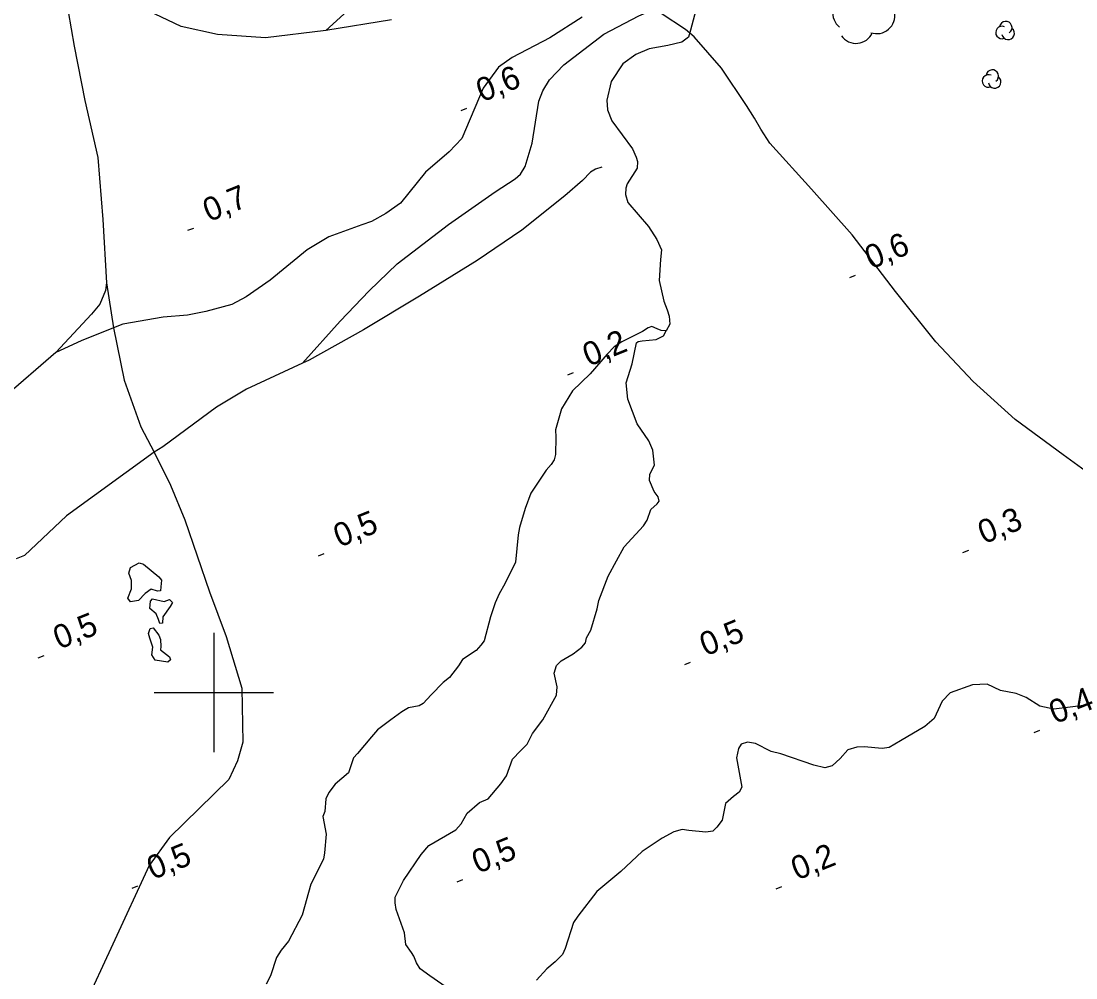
# Model space of a CAD drawing. Extents: x 362852 to 366875, y 5563573 to 5566479.
# Drawn here: x 363367.7 to 363544.5, y 5564552.2 to 5564712.5 of the extents above; entities that cross this region are included whole.
import ezdxf

# ---------------------------------------------------------------- set-up
doc = ezdxf.new("R2010")
doc.units = 0
for name, color, linetype in [('Niveau 22', 7, 'Continuous'), ('Niveau 3', 7, 'Continuous'), ('Niveau 4', 7, 'Continuous'), ('Niveau 44', 7, 'Continuous'), ('Niveau 61', 7, 'Continuous')]:
    doc.layers.add(name, color=color, linetype=linetype)

msp = doc.modelspace()

# ---------------------------------------------------------------- linework, layer by layer
at = {"layer": 'Niveau 22'}
for points in [[(363372.56, 5564730.65), (363374.35, 5564722.3), (363375.59, 5564714.1), (363376.59, 5564708.3), (363378.34, 5564699.18), (363380.56, 5564689.64), (363381.4, 5564679.26), (363381.97, 5564668.64), (363381.81, 5564667.38), (363380.9, 5564665.06), (363379.47, 5564663.39), (363373.52, 5564656.94), (363364.72, 5564649.35), (363357.31, 5564643.43), (363347.84, 5564635.44), (363341.7, 5564631.55), (363336.34, 5564630.55), (363330.76, 5564630.6), (363323.85, 5564630.91), (363322.1, 5564630.74), (363321.01, 5564630.34), (363314.56, 5564626.13), (363309.38, 5564623.38)], [(363429.79, 5564712.7), (363418.74, 5564710.95), (363408.63, 5564709.7), (363400.58, 5564710.26), (363394.5, 5564711.6), (363388.96, 5564714.25)], [(363414.85, 5564655.16), (363421.15, 5564662.19), (363426.03, 5564667.31), (363430.7, 5564671.8), (363439.33, 5564678.44), (363447.12, 5564683.89), (363450.47, 5564686.05), (363451.38, 5564686.87), (363452.17, 5564688.14), (363453.36, 5564692.03), (363454.47, 5564699.09), (363455.13, 5564700.81), (363456.26, 5564702.68), (363458.66, 5564705.19), (363465.35, 5564710.33), (363471.24, 5564713.41), (363473.19, 5564714.21)], [(363422.37, 5564714.23), (363418.74, 5564710.95)], [(363461.7, 5564713.16), (363456.29, 5564709.68), (363449.98, 5564706.41), (363447.72, 5564704.77), (363445.13, 5564701.29), (363441.56, 5564692.84), (363439.42, 5564690.62), (363435.47, 5564687.17), (363431.29, 5564682.02), (363428.84, 5564680.24), (363426.44, 5564678.92), (363424.8, 5564678.35), (363419.24, 5564676.34), (363415.63, 5564674.19), (363409.43, 5564669.08), (363405.38, 5564666.31), (363402.99, 5564664.99), (363398.67, 5564663.82), (363395.6, 5564663.22), (363391.51, 5564662.87), (363384.72, 5564661.71), (363383.19, 5564661.1), (363377.77, 5564658.91), (363373.52, 5564656.94)], [(363591.25, 5564651.45), (363586.11, 5564648.75), (363576.37, 5564643.16), (363565.69, 5564637.69), (363555.98, 5564635.37), (363549.87, 5564635.14), (363547.27, 5564636.24), (363542.38, 5564639.84), (363534.31, 5564645.74), (363527.29, 5564652.09), (363520.99, 5564658.78), (363514.26, 5564667.21), (363506.98, 5564676.7), (363500.15, 5564684.36), (363493.16, 5564692.03), (363491.7, 5564694.39), (363490.61, 5564696.25), (363489.27, 5564698.38), (363485.11, 5564704.62), (363480.49, 5564709.89), (363479.07, 5564711.1), (363474.99, 5564713.78)], [(363465.05, 5564688.02), (363463.94, 5564687.68), (363463.13, 5564687.21), (363461.79, 5564685.77), (363458.82, 5564683.22), (363451.62, 5564677.49), (363444.14, 5564672.36), (363434.45, 5564666.39), (363425.08, 5564660.76), (363415.98, 5564655.68), (363414.85, 5564655.16), (363405.46, 5564650.83), (363400.46, 5564647.79), (363391.41, 5564641.17), (363389.98, 5564640.26), (363375.3, 5564629.57), (363368.23, 5564622.96), (363366.83, 5564622.36)], [(363381.97, 5564668.64), (363383.19, 5564661.1), (363384.93, 5564652.31), (363387.73, 5564644.52), (363389.98, 5564640.26), (363392.73, 5564634.76), (363395.12, 5564628.93), (363399.25, 5564616.85), (363402.08, 5564609.37), (363404.7, 5564600.74), (363404.86, 5564591.66), (363403.93, 5564588.51), (363402.51, 5564585.39), (363392.53, 5564575.68), (363389.16, 5564571), (363383.06, 5564557.82), (363378.18, 5564547.28), (363377.99, 5564545.39), (363378.39, 5564544.43), (363378.92, 5564543.46), (363383.52, 5564541.38)]]:
    msp.add_lwpolyline(points, dxfattribs=at)
at = {"layer": 'Niveau 3'}
for p, q in [((363441.46, 5564697.51), (363442.42, 5564697.9)), ((363395.65, 5564677.44), (363396.61, 5564677.83)), ((363506.61, 5564669.51), (363507.57, 5564669.9)), ((363459.31, 5564653.2), (363460.27, 5564653.59)), ((363525.56, 5564623.45), (363526.52, 5564623.84)), ((363417.54, 5564622.89), (363418.5, 5564623.28)), ((363370.56, 5564605.8), (363371.52, 5564606.19)), ((363478.92, 5564604.66), (363479.88, 5564605.05)), ((363537.5, 5564593.3), (363538.46, 5564593.69)), ((363386.27, 5564567.2), (363387.23, 5564567.59)), ((363440.75, 5564568.23), (363441.71, 5564568.62)), ((363494.25, 5564567.1), (363495.21, 5564567.49))]:
    msp.add_line(p, q, dxfattribs=at)
at = {"layer": 'Niveau 4'}
for points in [[(363481.2, 5564716.01), (363479.91, 5564710.96), (363479.55, 5564709.82), (363478.46, 5564708.99), (363476.11, 5564708.44), (363472.96, 5564707.87), (363470.72, 5564706.93), (363468.54, 5564705.34), (363466.61, 5564702.41), (363465.85, 5564699.27), (363466, 5564697.65), (363466.71, 5564695.81), (363470.14, 5564691.1), (363470.79, 5564689.71), (363470.98, 5564688.97), (363470.93, 5564687.88), (363469.25, 5564685.24)], [(363469.25, 5564685.24), (363469.05, 5564684.53), (363469, 5564683.44), (363469.38, 5564682.09), (363472.83, 5564678.08), (363474.27, 5564675.93), (363475.01, 5564674.17), (363474.87, 5564672.54), (363474.61, 5564669.05), (363475.4, 5564665.55), (363476, 5564664.11), (363476.32, 5564663.05), (363476.44, 5564661.72), (363475.82, 5564660.59)], [(363440.96, 5564549.2), (363436.17, 5564552.53), (363434.56, 5564553.68), (363433.95, 5564554.68), (363433.53, 5564555.82), (363433.1, 5564556.4), (363432.15, 5564557.76), (363431.97, 5564559.69), (363430.57, 5564563.62), (363430.36, 5564564.73), (363430.39, 5564565.69), (363431.8, 5564568.48), (363434.73, 5564572.85), (363436.05, 5564574.35), (363440.53, 5564576.98), (363441.43, 5564577.99), (363442.43, 5564579.79), (363444.52, 5564581.55), (363445.96, 5564582.15), (363448.1, 5564584.68), (363449.05, 5564586.02), (363450.06, 5564588.84), (363451.37, 5564590.2), (363452.48, 5564591.3), (363453.41, 5564593.13), (363455.14, 5564595.43), (363457.44, 5564599.54), (363457.53, 5564600.96), (363457.01, 5564603.25), (363457.43, 5564604.49), (363458.23, 5564605.27), (363460.23, 5564606.49), (363461.65, 5564607.59), (363462.3, 5564608.3), (363462.46, 5564609.12), (363463.17, 5564610.42), (363464.23, 5564614.01), (363464.53, 5564615.39), (363466.07, 5564619.5), (363467.46, 5564622.03), (363468.79, 5564624.4), (363472.03, 5564627.9), (363472.63, 5564628.85), (363473.25, 5564630.68), (363474.3, 5564631.62), (363474.61, 5564632.07), (363474.45, 5564632.75), (363473.81, 5564633.68), (363473.02, 5564635.54), (363473.09, 5564636.58), (363473.84, 5564638.09), (363473.59, 5564640.62), (363472.89, 5564642.15), (363470.92, 5564645.03), (363469.38, 5564649.15), (363469.12, 5564651.87), (363470.11, 5564655.05), (363470.81, 5564658.61), (363471.11, 5564658.8), (363471.81, 5564658.91), (363474.11, 5564659.12), (363475.35, 5564659.76), (363475.82, 5564660.59), (363474.97, 5564660.67), (363474.29, 5564660.95), (363473.43, 5564661.35), (363472.79, 5564661.08), (363471.84, 5564660.49), (363469.83, 5564659.46), (363468.35, 5564658.77), (363467.08, 5564657.92), (363465.91, 5564656.68), (363463.07, 5564653.41), (363460.08, 5564650.52), (363458.27, 5564647.5), (363457.23, 5564643.99), (363457.31, 5564642.76), (363457.27, 5564639.86), (363457.01, 5564638.99), (363456.51, 5564638.22), (363455.67, 5564637.24), (363453.13, 5564633.41), (363452.16, 5564630.8), (363451.22, 5564627.65), (363450.98, 5564626.41), (363450.58, 5564621.85), (363448.78, 5564618.2), (363447.79, 5564616.53)], [(363389.46, 5564617.28), (363388.45, 5564616.55), (363387.37, 5564615.4), (363386, 5564615.2), (363385.57, 5564615.78), (363386.17, 5564617.35), (363386.21, 5564618.74), (363385.75, 5564619.99), (363385.99, 5564620.91), (363387.47, 5564621.72), (363388.21, 5564621.47), (363390.79, 5564619.35), (363391.2, 5564618.83), (363391.12, 5564617.67), (363391.03, 5564617), (363390.53, 5564616.98), (363389.46, 5564617.28)], [(363390.93, 5564611.56), (363390.71, 5564612.22), (363390.31, 5564613.18), (363389.25, 5564614.05), (363389.36, 5564615.29), (363389.69, 5564615.68), (363391.64, 5564615.24), (363392.57, 5564615.57), (363393.03, 5564615.07), (363392.67, 5564614.42), (363391.41, 5564612.64), (363391.4, 5564611.63), (363390.93, 5564611.56)], [(363447.79, 5564616.53), (363447.12, 5564614.99), (363446.34, 5564612.65), (363445.32, 5564608.65), (363444.75, 5564607.9), (363443.94, 5564607), (363441.69, 5564605.49), (363441, 5564604.44), (363439.49, 5564602.49), (363438.4, 5564601.65), (363436.44, 5564599.58), (363435.1, 5564598.13), (363434.38, 5564597.77), (363432.64, 5564597.42), (363431.48, 5564596.74), (363429.65, 5564595.41), (363427.41, 5564593.71), (363426.4, 5564592.53), (363424.04, 5564589.78), (363423.42, 5564589.02), (363422.58, 5564586.53), (363420.3, 5564584.63), (363419.25, 5564583.25), (363418.76, 5564582.16), (363418.57, 5564580.07), (363418.25, 5564579.18), (363418.79, 5564576.27), (363418.55, 5564573.09), (363418.36, 5564572.07), (363416.23, 5564567.84), (363414.78, 5564562.65), (363412.52, 5564558.3), (363411.27, 5564556.78), (363410.47, 5564555.56), (363409.49, 5564552.51), (363408.75, 5564551.13)], [(363389.84, 5564610.85), (363390.74, 5564609.6), (363391.06, 5564608.85), (363391.11, 5564607.68), (363391.02, 5564607.14), (363392.53, 5564605.95), (363392.73, 5564605.47), (363392.26, 5564605.08), (363390.18, 5564605.4), (363389.62, 5564606.3), (363389.78, 5564607.56), (363389.26, 5564609.1), (363389.05, 5564609.89), (363389.34, 5564610.7), (363389.84, 5564610.85)], [(363546.25, 5564597.84), (363540.79, 5564597.19), (363538.44, 5564597.71), (363536.17, 5564599.15), (363534.45, 5564599.81), (363531.84, 5564600.34), (363529.63, 5564601.36), (363527.16, 5564601.27), (363523.4, 5564599.95), (363522.06, 5564598.51), (363520.75, 5564595.64), (363519.18, 5564594.29), (363515.08, 5564591.88), (363513.2, 5564590.78), (363512.02, 5564590.59), (363509, 5564590.9), (363507.78, 5564590.82), (363506.27, 5564590.38), (363504.96, 5564588.95), (363503.66, 5564587.72), (363502.41, 5564587.38), (363500.55, 5564587.79), (363495.01, 5564589.73), (363493.43, 5564590.09), (363490.8, 5564591.43), (363489.44, 5564591.68), (363488.4, 5564591.31), (363487.94, 5564590.61), (363487.6, 5564589.02), (363488.47, 5564584.11), (363488.06, 5564583.31), (363487.12, 5564582.54), (363485.78, 5564581.41), (363485.2, 5564578.59), (363484.32, 5564577.4), (363483.65, 5564576.75), (363482.47, 5564576.57), (363479.59, 5564576.86), (363478.51, 5564577.04), (363477.1, 5564576.64), (363475.11, 5564575.55), (363471.77, 5564573.33), (363468.21, 5564570.01), (363464.17, 5564566.62), (363460.99, 5564562.52), (363460.25, 5564561.45), (363458.87, 5564557.1), (363458.41, 5564556.1), (363457.19, 5564554.83), (363455.79, 5564553.67), (363454.08, 5564551.76)]]:
    msp.add_lwpolyline(points, dxfattribs=at)
at = {"layer": 'Niveau 44'}
for centre, radius, start, end in [((363506.72, 5564713.86), 3, 112.2212, 232.1991), ((363511.12, 5564713.4), 3, 250.9081, 10.886), ((363532.73, 5564711.42), 1.05, 304.3592, 171.8163), ((363507.64, 5564711.77), 3, 215.2609, 335.2388), ((363532.09, 5564710.6), 1.05, 66.2054, 291.894), ((363533.12, 5564710.45), 1.05, 189.0269, 51.7112), ((363529.84, 5564702.47), 1.05, 66.2054, 291.894), ((363530.48, 5564703.29), 1.05, 304.3592, 171.8163), ((363530.87, 5564702.32), 1.05, 189.0269, 51.7112)]:
    msp.add_arc(centre, radius, start, end, dxfattribs=at)
at = {"layer": 'Niveau 61'}
for p, q in [((363400, 5564610), (363400, 5564590)), ((363390, 5564600), (363410, 5564600))]:
    msp.add_line(p, q, dxfattribs=at)

# ---------------------------------------------------------------- texts
at = {"layer": 'Niveau 3'}
for s, p in [('0,6  ', (363444.97, 5564698.87)), ('0,7  ', (363399.16, 5564678.8)), ('0,6  ', (363510.12, 5564670.87)), ('0,2  ', (363462.82, 5564654.56)), ('0,3  ', (363529.07, 5564624.81)), ('0,5  ', (363421.05, 5564624.25)), ('0,5  ', (363374.07, 5564607.16)), ('0,5  ', (363482.43, 5564606.02)), ('0,4  ', (363541.01, 5564594.66)), ('0,5  ', (363389.78, 5564568.56)), ('0,5  ', (363444.26, 5564569.59)), ('0,2  ', (363497.76, 5564568.46))]:
    msp.add_text(s, height=3.93, rotation=22.09, dxfattribs=at).set_placement(p)

doc.saveas('drawing.dxf')
